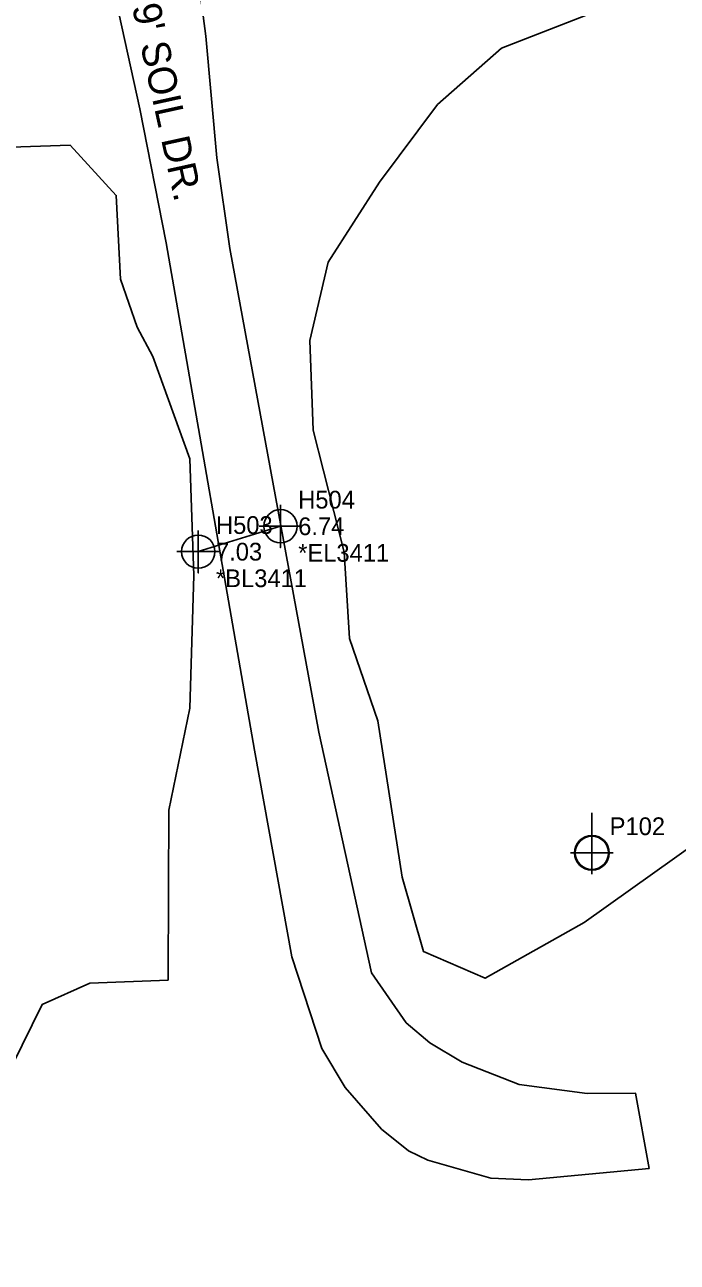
# Model space of a CAD drawing. Extents: x 2597630 to 2605918, y 617194 to 635093.
# Drawn here: x 2603559.5 to 2603651.5, y 618264.7 to 618439.2 of the extents above; entities that cross this region are included whole.
import ezdxf

# ---------------------------------------------------------------- set-up
doc = ezdxf.new("R2010")
doc.units = 0
for name, color, linetype in [('Cogo Default Point CELL', 7, 'Continuous'), ('COGO Default Point Number', 7, 'Continuous'), ('Exist Other Culture Gate', 7, 'Continuous'), ('Exist Other Culture Gate Cogo Comment', 7, 'Continuous'), ('Exist Other Culture Gate Cogo Elevation', 7, 'Continuous'), ('Exist Other Culture Gate Cogo Number', 7, 'Continuous'), ('Exist Other Culture Gate Cogo Point CELL', 7, 'Continuous'), ('Exist Roads EOP', 7, 'Continuous'), ('Exist Roads Soil', 7, 'Continuous'), ('Exist Roads Soil Text', 7, 'Continuous'), ('Exist Utilities Power Pole CELL', 7, 'Continuous'), ('Exist Vegetation Woods Line', 7, 'Continuous')]:
    doc.layers.add(name, color=color, linetype=linetype)

# ---------------------------------------------------------------- blocks, each defined once
blk = doc.blocks.new('EXIST OTHER CULTURE GATE COGO POINT')
at = {"layer": 'Exist Other Culture Gate Cogo Point CELL'}
blk.add_lwpolyline([(0, 0.06), (0, -0.06), (0, 0), (0.06, 0), (-0.06, 0)], dxfattribs=at)
blk.add_circle((0, 0), 0.0469, dxfattribs=at)
blk = doc.blocks.new('COGO DEFAULT POINT')
at = {"layer": 'Cogo Default Point CELL'}
for points in [[(0, 0.06), (0, 0)], [(-0.06, 0), (0, 0)], [(0, 0), (0.06, 0)], [(0, 0), (0, -0.06)]]:
    blk.add_lwpolyline(points, dxfattribs=at)
blk.add_circle((0, 0), 0.0469, dxfattribs=at)

msp = doc.modelspace()

# ---------------------------------------------------------------- linework, layer by layer
at = {"layer": 'Exist Other Culture Gate'}
msp.add_line((2603584, 618364.87), (2603595.59, 618368.45), dxfattribs=at)
at = {"layer": 'Exist Roads EOP'}
for points in [[(2603230.17, 618389.98), (2603282.93, 618409.6), (2603332.77, 618427.87), (2603388.17, 618448.41), (2603437.2, 618466.72), (2603490.78, 618486.53), (2603539.04, 618504.56), (2603597.45, 618526.16), (2603651.05, 618545.97), (2603705.21, 618566.08), (2603762.02, 618587.18), (2603820.33, 618609.16), (2603876.34, 618629.99), (2603934.91, 618652.28), (2603996.41, 618675.57), (2604033.22, 618689.96), (2604052.01, 618697.2)], [(2604034.63, 618668.49), (2603984.89, 618650.12), (2603936.77, 618631.65), (2603888.19, 618613.33), (2603837.77, 618594.26), (2603782.92, 618573.7), (2603731.94, 618554.39), (2603671.13, 618532.17), (2603621.82, 618514.11), (2603561.54, 618491.88), (2603506.42, 618471.29), (2603452.16, 618451.33), (2603398.36, 618431.32), (2603341.43, 618410.35), (2603281.65, 618388.2), (2603223.03, 618366.47), (2603185.72, 618352.61)]]:
    msp.add_spline(points, degree=3, dxfattribs=at)
at = {"layer": 'Exist Roads Soil'}
for points in [[(2603647.56, 618277.9), (2603645.63, 618288.54), (2603638.85, 618288.46), (2603629.22, 618289.77), (2603621.2, 618292.91), (2603616.63, 618295.64), (2603613.32, 618298.45), (2603608.43, 618305.5), (2603600.99, 618339.42), (2603588.46, 618407.61), (2603586.62, 618420.38), (2603585.06, 618437.53), (2603582.12, 618460.18), (2603580.21, 618474.31), (2603580.01, 618482.56), (2603580.24, 618487.47), (2603581.03, 618491.32), (2603582.63, 618495.32), (2603584.71, 618498.43), (2603586.81, 618501.22)], [(2603647.56, 618277.9), (2603630.58, 618276.31), (2603625.27, 618276.54), (2603616.38, 618279.09), (2603613.64, 618280.38), (2603609.85, 618283.46), (2603604.69, 618289.32), (2603601.43, 618294.84), (2603597.2, 618307.77), (2603591.92, 618336.9), (2603579.49, 618408.43), (2603575.76, 618427.29), (2603571.94, 618444.71)]]:
    msp.add_lwpolyline(points, dxfattribs=at)
at = {"layer": 'Exist Utilities Power Pole CELL'}
for q in [(2603639.5, 618328.04), (2603639.5, 618322.41)]:
    msp.add_line((2603639.5, 618322.41), q, dxfattribs=at)
msp.add_circle((2603639.5, 618322.41), 2.45, dxfattribs=at)
at = {"layer": 'Exist Vegetation Woods Line'}
for points in [[(2603654.58, 618324.11), (2603638.41, 618312.57), (2603624.43, 618304.74), (2603615.75, 618308.48), (2603612.75, 618319), (2603609.3, 618341.02), (2603605.33, 618352.65), (2603604.56, 618364.79), (2603600.2, 618382.01), (2603599.74, 618394.63), (2603602.33, 618405.69), (2603609.56, 618416.97), (2603617.75, 618427.93), (2603626.77, 618435.87), (2603648.74, 618444.44)], [(2603404.78, 618375.15), (2603492.48, 618400.62), (2603509.77, 618408.05), (2603527.07, 618416.43), (2603549.15, 618421.6), (2603565.93, 618422.16), (2603572.45, 618415.1), (2603573.03, 618403.27), (2603575.4, 618396.54), (2603577.62, 618392.38), (2603582.82, 618377.97), (2603583.38, 618361.51), (2603582.81, 618342.81), (2603579.86, 618328.45), (2603579.81, 618317.42), (2603579.75, 618304.47), (2603568.72, 618304.05), (2603561.99, 618301.04), (2603556.35, 618289.57), (2603535.06, 618282), (2603162.7, 618163.62)]]:
    msp.add_lwpolyline(points, dxfattribs=at)

# ---------------------------------------------------------------- block references
at = {"layer": 'Cogo Default Point CELL', "xscale": 50, "yscale": 50}
msp.add_blockref('COGO DEFAULT POINT', (2603639.5, 618322.41), dxfattribs=at)
at = {"layer": 'Exist Other Culture Gate Cogo Point CELL', "xscale": 50, "yscale": 50}
for p in [(2603595.59, 618368.45), (2603595.59, 618368.45), (2603584, 618364.87), (2603584, 618364.87)]:
    msp.add_blockref('EXIST OTHER CULTURE GATE COGO POINT', p, dxfattribs=at)

# ---------------------------------------------------------------- texts
at = {"layer": 'COGO Default Point Number'}
msp.add_text('P102', height=2.5, dxfattribs=at).set_placement((2603642, 618324.91))
at = {"layer": 'Exist Other Culture Gate Cogo Comment'}
for s, p in [('*EL3411', (2603598.09, 618363.45)), ('*EL3411', (2603598.09, 618363.45)), ('*BL3411', (2603586.5, 618359.87)), ('*BL3411', (2603586.5, 618359.87))]:
    msp.add_text(s, height=2.5, dxfattribs=at).set_placement(p)
at = {"layer": 'Exist Other Culture Gate Cogo Elevation'}
for s, p in [('6.74', (2603598.09, 618367.2)), ('6.74', (2603598.09, 618367.2)), ('7.03', (2603586.5, 618363.62)), ('7.03', (2603586.5, 618363.62))]:
    msp.add_text(s, height=2.5, dxfattribs=at).set_placement(p)
at = {"layer": 'Exist Other Culture Gate Cogo Number'}
for s, p in [('H504', (2603598.09, 618370.95)), ('H504', (2603598.09, 618370.95)), ('H503', (2603586.5, 618367.37)), ('H503', (2603586.5, 618367.37))]:
    msp.add_text(s, height=2.5, dxfattribs=at).set_placement(p)
at = {"layer": 'Exist Roads Soil Text'}
msp.add_text("9' SOIL DR.", height=4, rotation=282.3687, dxfattribs=at).set_placement((2603574.64, 618441.73))

doc.saveas('drawing.dxf')
